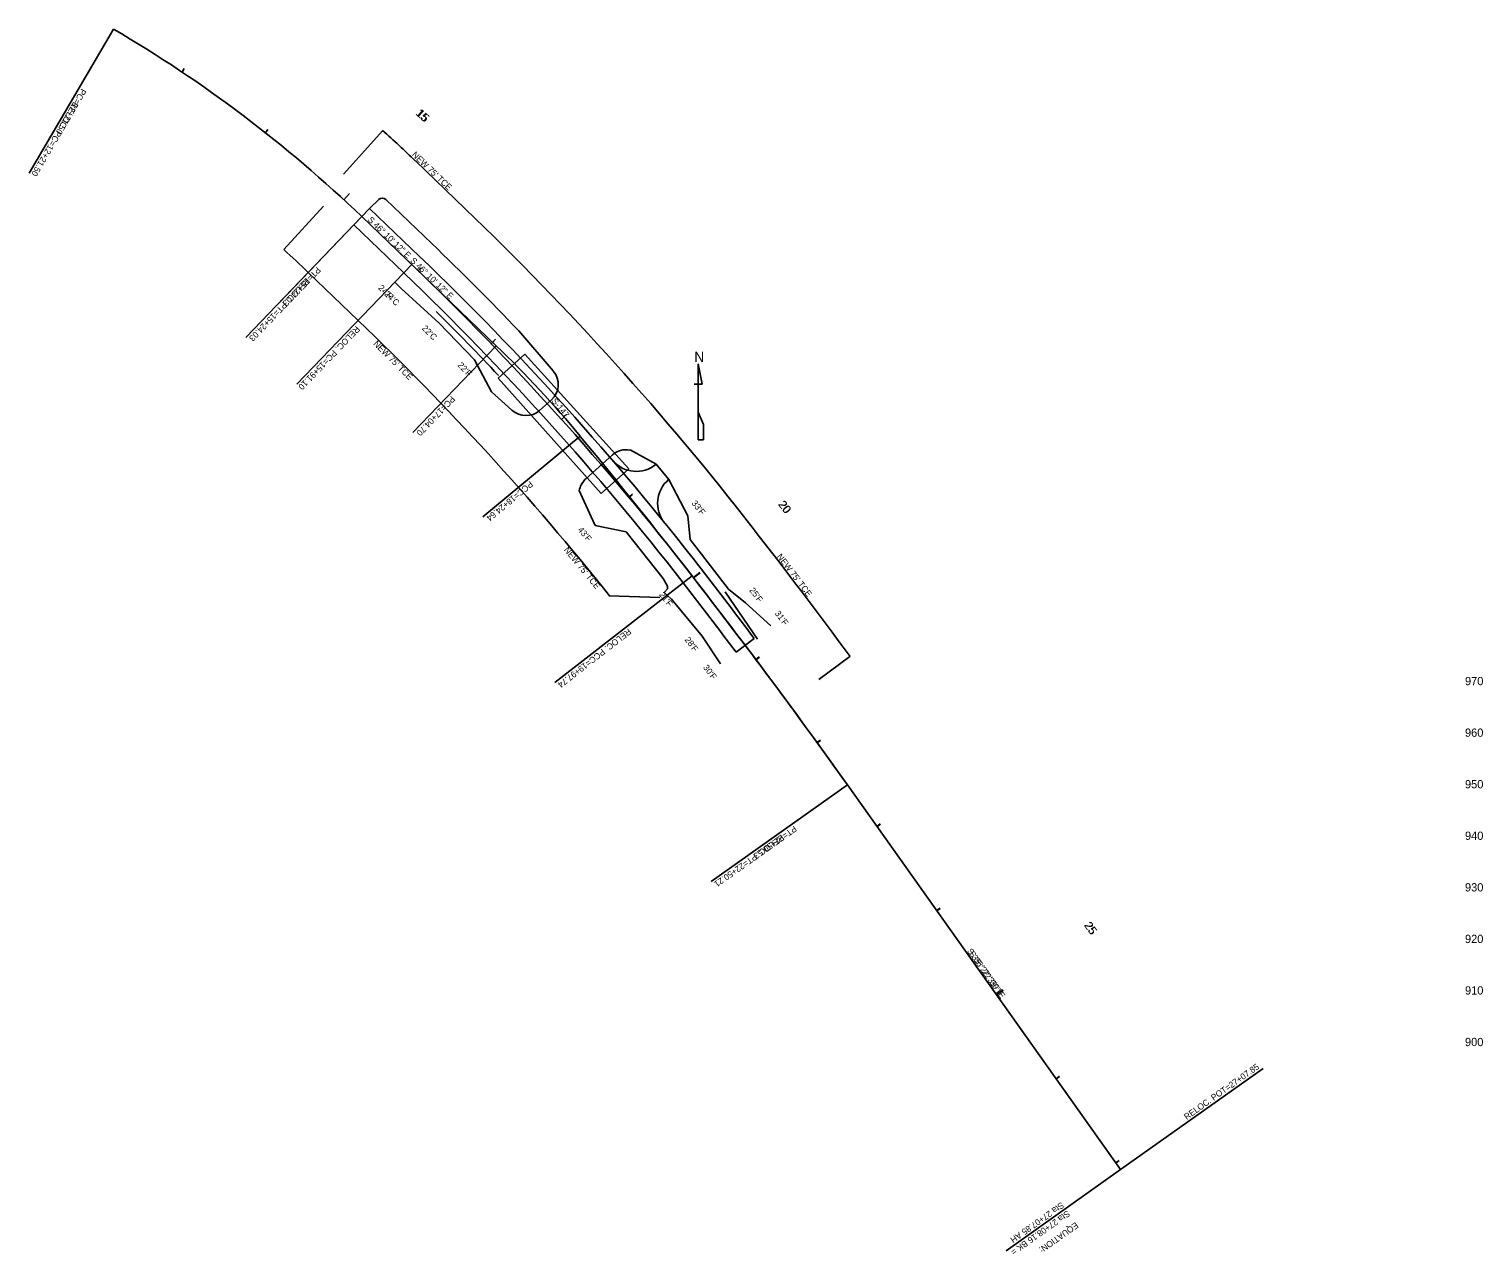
# Model space of a CAD drawing. Extents: x 1573485 to 1576468, y 1104256 to 1106756.
# Drawn here: x 1573485 to 1574895, y 1105306 to 1106493 of the extents above; entities that cross this region are included whole.
import ezdxf

# ---------------------------------------------------------------- set-up
doc = ezdxf.new("R2010")
doc.units = 0
for name, color, linetype in [('RD_DDB_ElevTX', 7, 'Continuous'), ('RD_EX_Misc', 7, 'Continuous'), ('RD_EX_RW', 7, 'Continuous'), ('RD_HC_Cl', 7, 'Continuous'), ('RD_HC_CL_Rel', 7, 'Continuous'), ('RD_HC_Data', 7, 'Continuous'), ('RD_HC_Data_Rel', 7, 'Continuous'), ('RD_HC_Data_Tic', 7, 'Continuous'), ('RD_HC_Data_Tic_Rel', 7, 'Continuous'), ('RD_HC_TX_Rel_Sta50', 7, 'Continuous'), ('RD_PD_Bridge', 7, 'Continuous'), ('RD_PD_CstnLmt', 7, 'Continuous'), ('RD_PD_CstnLmt_TX', 7, 'Continuous'), ('RD_PD_Driveway', 7, 'Continuous'), ('RD_PD_Final_TrvlWay', 7, 'Continuous'), ('RD_PD_GR', 7, 'Continuous'), ('RD_PD_RW', 7, 'Continuous'), ('RD_PD_RW_TX', 7, 'Continuous'), ('RD_TX_RoadID', 7, 'Continuous')]:
    doc.layers.add(name, color=color, linetype=linetype)

msp = doc.modelspace()

# ---------------------------------------------------------------- linework, layer by layer
at = {"layer": 'RD_EX_Misc'}
for p, q in [((1574138.2, 1106149), (1574134.3, 1106168.6)), ((1574134.3, 1106168.6), (1574134.3, 1106168.6)), ((1574134.3, 1106168.6), (1574134.3, 1106149)), ((1574130.4, 1106149), (1574134.3, 1106149)), ((1574134.3, 1106121.8), (1574134.3, 1106149)), ((1574134.3, 1106149), (1574138.2, 1106149)), ((1574138.2, 1106149), (1574138.2, 1106149.3)), ((1574139.2, 1106109.8), (1574134.3, 1106121.8)), ((1574134.3, 1106121.8), (1574134.3, 1106095.1)), ((1574139.2, 1106095.1), (1574139.2, 1106110)), ((1574139.2, 1106110), (1574139.2, 1106109.8)), ((1574134.3, 1106095.1), (1574139.2, 1106095.1))]:
    msp.add_line(p, q, dxfattribs=at)
at = {"layer": 'RD_HC_Cl'}
for p, q in [((1573808, 1106311.5), (1573938.4, 1106186.3)), ((1574278.9, 1105760.5), (1574543.8, 1105387.4))]:
    msp.add_line(p, q, dxfattribs=at)
for centre, radius, start, end in [((1572920.8, 1105387.3), 1281.1, 46.1701, 59.7005), ((1573219.8, 1105437.8), 1037.6, 39.5471, 46.1701), ((1569507.3, 1102372.3), 5852.1, 35.37737, 39.54707)]:
    msp.add_arc(centre, radius, start, end, dxfattribs=at)
at = {"layer": 'RD_HC_CL_Rel'}
for p, q in [((1573808, 1106311.5), (1573856.4, 1106265)), ((1574278.9, 1105760.5), (1574543.8, 1105387.4))]:
    msp.add_line(p, q, dxfattribs=at)
for centre, radius, start, end in [((1572920.8, 1105387.3), 1281.1, 46.1701, 59.7005), ((1571917.4, 1104245.1), 2800, 37.8491, 46.1701), ((1569507.3, 1102372.3), 5852.1, 35.37737, 37.84915)]:
    msp.add_arc(centre, radius, start, end, dxfattribs=at)
at = {"layer": 'RD_HC_Data'}
for p, q in [((1573567.2, 1106493.4), (1573508.3, 1106392.6)), ((1573808, 1106311.5), (1573728.1, 1106228.2)), ((1573938.4, 1106186.3), (1573857.5, 1106102.2)), ((1574019.9, 1106098.5), (1573925.4, 1106020.5)), ((1574278.9, 1105760.5), (1574184.7, 1105693.6)), ((1574543.8, 1105387.4), (1574432.8, 1105308.5))]:
    msp.add_line(p, q, dxfattribs=at)
at = {"layer": 'RD_HC_Data_Rel'}
for p, q in [((1573567.2, 1106493.4), (1573485.4, 1106353.5)), ((1573808, 1106311.5), (1573695.7, 1106194.4)), ((1573856.4, 1106265), (1573744.9, 1106148.9)), ((1574128.3, 1105963.1), (1573995.1, 1105859.6)), ((1574278.9, 1105760.5), (1574146.8, 1105666.7)), ((1574543.8, 1105387.4), (1574682.1, 1105485.5))]:
    msp.add_line(p, q, dxfattribs=at)
at = {"layer": 'RD_HC_Data_Tic'}
for p, q in [((1573633.7, 1106451.7), (1573635.9, 1106455)), ((1573714.5, 1106392.9), (1573717, 1106396)), ((1573790.5, 1106327.9), (1573796, 1106333.8)), ((1573862.8, 1106258.8), (1573865.6, 1106261.7)), ((1573935, 1106189.6), (1573937.7, 1106192.5)), ((1574004, 1106117.3), (1574007, 1106119.9)), ((1574067.5, 1106040), (1574070.6, 1106042.6)), ((1574129.5, 1105961.6), (1574135.8, 1105966.5)), ((1574190.2, 1105882.1), (1574193.4, 1105884.5)), ((1574249.4, 1105801.6), (1574252.7, 1105803.9)), ((1574307.5, 1105720.2), (1574310.8, 1105722.5)), ((1574365.4, 1105638.6), (1574368.7, 1105640.9)), ((1574423.3, 1105557.1), (1574429.8, 1105561.7)), ((1574481.2, 1105475.5), (1574484.5, 1105477.9)), ((1574539.1, 1105394), (1574542.4, 1105396.3))]:
    msp.add_line(p, q, dxfattribs=at)
at = {"layer": 'RD_HC_Data_Tic_Rel'}
for p, q in [((1573633.7, 1106451.7), (1573635.9, 1106455)), ((1573714.5, 1106392.9), (1573717, 1106396)), ((1573790.5, 1106327.9), (1573796, 1106333.8)), ((1573862.8, 1106258.8), (1573865.6, 1106261.7)), ((1573933.5, 1106188.1), (1573936.4, 1106190.9)), ((1574001.6, 1106114.9), (1574004.5, 1106117.5)), ((1574067, 1106039.2), (1574070.1, 1106041.8)), ((1574129.7, 1105961.3), (1574136, 1105966.2)), ((1574190.3, 1105881.8), (1574193.6, 1105884.2)), ((1574249.6, 1105801.3), (1574252.9, 1105803.6)), ((1574307.7, 1105719.9), (1574311, 1105722.2)), ((1574365.6, 1105638.4), (1574368.9, 1105640.7)), ((1574423.5, 1105556.8), (1574430, 1105561.5)), ((1574481.4, 1105475.3), (1574484.7, 1105477.6)), ((1574539.3, 1105393.7), (1574542.5, 1105396.1))]:
    msp.add_line(p, q, dxfattribs=at)
at = {"layer": 'RD_PD_Bridge'}
for p, q in [((1573940.1, 1106154.9), (1573966.1, 1106178.1)), ((1573966.1, 1106178.1), (1573966.1, 1106178.1)), ((1573966.1, 1106178.1), (1574066.9, 1106067)), ((1574040, 1106043), (1573940.1, 1106154.9)), ((1574040, 1106043), (1574066.9, 1106067))]:
    msp.add_line(p, q, dxfattribs=at)
at = {"layer": 'RD_PD_CstnLmt'}
for p, q in [((1573824.4, 1106328), (1573815.6, 1106319.4)), ((1573831.3, 1106328.1), (1573875.9, 1106285.3)), ((1573840.1, 1106248), (1573846.3, 1106241.7)), ((1573846.3, 1106241.7), (1573882.9, 1106208.2)), ((1573882.9, 1106208.2), (1573917.3, 1106172.5)), ((1573960.4, 1106200.7), (1573993.7, 1106161.8)), ((1573917.3, 1106172.5), (1573933.9, 1106141.6)), ((1573933.9, 1106141.6), (1573953.6, 1106123.7)), ((1573980.4, 1106123.5), (1573991.9, 1106133.8)), ((1574051.1, 1106080.4), (1574025.2, 1106057.3)), ((1574093.3, 1106071.3), (1574068.1, 1106085.2)), ((1574018.9, 1106045.9), (1574030.5, 1106020.3)), ((1574023.5, 1106055.6), (1574020.7, 1106051.5)), ((1574105.6, 1106056.6), (1574124.3, 1106021.2)), ((1574030.5, 1106020.3), (1574034.3, 1106011.9)), ((1574124.3, 1106021.2), (1574126.3, 1105998.5)), ((1574034.3, 1106011.9), (1574064.4, 1106005.8)), ((1574064.4, 1106005.8), (1574100.4, 1105960.7)), ((1574163.5, 1105950.3), (1574126.3, 1105998.5)), ((1574100.4, 1105960.7), (1574104.3, 1105953.1)), ((1574101.1, 1105947), (1574108.2, 1105940.4)), ((1574104.5, 1105950.5), (1574101.4, 1105947.2)), ((1574104.3, 1105953.1), (1574104.5, 1105950.5)), ((1574163.5, 1105950.3), (1574180.1, 1105936.9)), ((1574108.2, 1105940.4), (1574138, 1105904.8)), ((1574180.1, 1105936.9), (1574204.7, 1105914.6)), ((1574138, 1105904.8), (1574155.9, 1105877.8))]:
    msp.add_line(p, q, dxfattribs=at)
for centre, radius, start, end in [((1573827.9, 1106324.5), 5, 46.1701, 134.695), ((1571917.4, 1104245.1), 2828.1, 43.7467, 46.1701), ((1573978.6, 1106148.7), 20, 311.7692, 40.8659), ((1573967.1, 1106138.5), 20, 227.6827, 311.7692), ((1574064.4, 1106065.5), 20, 79.5037, 131.7692), ((1574038.6, 1106042.4), 20, 153.1235, 169.8444), ((1574038.6, 1106042.4), 20, 131.7692, 138.814)]:
    msp.add_arc(centre, radius, start, end, dxfattribs=at)
at = {"layer": 'RD_PD_Driveway'}
msp.add_line((1574093.3, 1106071.3), (1574105.6, 1106056.6), dxfattribs=at)
for centre, start, end in [((1574074.1, 1106094.4), 220.6111, 309.8492), ((1574124.8, 1106033.5), 129.8492, 219.0143)]:
    msp.add_arc(centre, 30, start, end, dxfattribs=at)
at = {"layer": 'RD_PD_Final_TrvlWay'}
for p, q in [((1573800.4, 1106303.5), (1573815.6, 1106319.4)), ((1573815.6, 1106319.4), (1573864, 1106272.9)), ((1573800.4, 1106303.5), (1573848.8, 1106257.1)), ((1574188.6, 1105902.4), (1574171.1, 1105889.2))]:
    msp.add_line(p, q, dxfattribs=at)
for centre, radius, start, end in [((1571917.4, 1104245.1), 2811, 37.8491, 46.1701), ((1571917.4, 1104245.1), 2789, 37.8491, 46.1701), ((1569507.3, 1102372.3), 5863.1, 37.01932, 37.84915), ((1569507.3, 1102372.3), 5841.1, 37.01932, 37.84915)]:
    msp.add_arc(centre, radius, start, end, dxfattribs=at)
at = {"layer": 'RD_PD_GR'}
msp.add_line((1574191.6, 1105901.7), (1574160.4, 1105947.7), dxfattribs=at)
msp.add_arc((1571917.4, 1104245.1), 2784, 43.3881, 45.1677, dxfattribs=at)
at = {"layer": 'RD_PD_RW'}
for p, q in [((1573790.2, 1106352.6), (1573828.3, 1106395)), ((1573860, 1106365.6), (1573908.3, 1106319.1)), ((1573770.8, 1106321.6), (1573732.4, 1106279.5)), ((1573756.1, 1106257.3), (1573804.5, 1106210.9)), ((1574097, 1105942.1), (1574048, 1105943.8)), ((1574251.2, 1105862.7), (1574281.4, 1105885))]:
    msp.add_line(p, q, dxfattribs=at)
for centre, radius, start, end in [((1572920.8, 1105387.3), 1356.1, 46.1701, 47.9971), ((1571917.4, 1104245.1), 2875, 37.8491, 46.1701), ((1572920.8, 1105387.3), 1206.1, 46.1701, 47.7087), ((1571917.4, 1104245.1), 2725, 38.5645, 46.1701), ((1569507.3, 1102372.3), 5927.1, 36.34419, 37.84915)]:
    msp.add_arc(centre, radius, start, end, dxfattribs=at)

# ---------------------------------------------------------------- texts
at = {"layer": 'RD_DDB_ElevTX'}
for s, p in [('970', (1574877.7, 1105857.1)), ('960', (1574877.7, 1105807.1)), ('950', (1574877.7, 1105757.1)), ('940', (1574877.7, 1105707.1)), ('930', (1574877.7, 1105657.1)), ('920', (1574877.7, 1105607.1)), ('910', (1574877.7, 1105557.1)), ('900', (1574877.7, 1105507.1))]:
    msp.add_text(s, height=8, dxfattribs=at).set_placement(p)
at = {"layer": 'RD_EX_Misc'}
msp.add_text('N', height=10, dxfattribs=at).set_placement((1574130.4, 1106170.5))
at = {"layer": 'RD_EX_RW'}
for s, rotation, p in [('15', 317.2448, (1573859.6, 1106411.1)), ('20', 307.8302, (1574211.3, 1106032.4)), ('25', 305.3774, (1574508, 1105624.3))]:
    msp.add_text(s, height=8, rotation=rotation, dxfattribs=at).set_placement(p)
at = {"layer": 'RD_HC_Data'}
for s, rotation, p in [('PC=12+21.50', 239.7005, (1573536.1, 1106436.2)), ('S 46%%d 10\' 12" E', 316.1701, (1573854.5, 1106268.2)), ('PT=15+24.03', 226.1701, (1573764.5, 1106263.2)), ('PC=17+04.70', 226.1701, (1573894.8, 1106138.1)), ('PCC=18+24.64', 219.5471, (1573971, 1106055.5)), ('PT=22+50.53', 215.3774, (1574227, 1105721.2)), ('S 35%%d 22\' 39" E', 305.3774, (1574394.6, 1105599.2)), ('Sta 27+07.85 AH', 215.3774, (1574486.2, 1105356.2)), ('Sta 27+08.16 BK = ', 215.3774, (1574492, 1105348.1)), ('EQUATION:', 215.3774, (1574500.1, 1105336.7))]:
    msp.add_text(s, height=6, rotation=rotation, dxfattribs=at).set_placement(p)
at = {"layer": 'RD_HC_Data_Rel'}
for s, rotation, p in [('RELOC. PC=12+21.50', 239.7005, (1573528.5, 1106423.3)), ('S 46%%d 10\' 12" E', 316.1701, (1573813.3, 1106307.8)), ('RELOC. PT=15+24.03', 226.1701, (1573754.1, 1106252.4)), ('RELOC. PC=15+91.10', 226.1701, (1573802.5, 1106205.9)), ('RELOC. PCC=19+97.74', 217.8491, (1574066.4, 1105912.5)), ('RELOC. PT=22+50.21', 215.3774, (1574214.8, 1105712.5)), ('S 35%%d 22\' 39" E', 305.3774, (1574396.4, 1105596.7)), ('RELOC. POT=27+07.85', 35.3774, (1574607.9, 1105435.3))]:
    msp.add_text(s, height=6, rotation=rotation, dxfattribs=at).set_placement(p)
at = {"layer": 'RD_HC_TX_Rel_Sta50'}
for s, rotation, p in [('15', 317.2448, (1573860.3, 1106410.5)), ('20', 307.827, (1574211.6, 1106032)), ('25', 305.3774, (1574508.3, 1105623.9))]:
    msp.add_text(s, height=8, rotation=rotation, dxfattribs=at).set_placement(p)
at = {"layer": 'RD_PD_CstnLmt_TX'}
for s, rotation, p in [("24'F", 316.1701, (1573823.5, 1106241.7)), ("24'C", 315.9881, (1573829.4, 1106235.8)), ("22'C", 314.9649, (1573865.9, 1106202.6)), ("22'F", 313.9418, (1573900.5, 1106166.9)), ("33'F", 308.8261, (1574127.4, 1106033.4)), ("43'F", 309.8492, (1574017.1, 1106007.5)), ("21'F", 307.827, (1574096, 1105944.8)), ("25'F", 307.3375, (1574183.4, 1105949)), ("31'F", 307.0193, (1574208.1, 1105926.6)), ("28'F", 307.3375, (1574120.7, 1105901.1)), ("30'F", 307.0193, (1574138.6, 1105874.2))]:
    msp.add_text(s, height=6, rotation=rotation, dxfattribs=at).set_placement(p)
at = {"layer": 'RD_PD_RW_TX'}
for rotation, p in [(316.1701, (1573856.1, 1106370.9)), (314.88, (1573818.8, 1106187.7)), (309.3436, (1574003.6, 1105988.1)), (307.2619, (1574210.1, 1105981.8))]:
    msp.add_text("NEW 75' TCE", height=6, rotation=rotation, dxfattribs=at).set_placement(p)
at = {"layer": 'RD_TX_RoadID'}
msp.add_text('S-147', height=6, rotation=308.9111, dxfattribs=at).set_placement((1573991.7, 1106132.5))

doc.saveas('drawing.dxf')
